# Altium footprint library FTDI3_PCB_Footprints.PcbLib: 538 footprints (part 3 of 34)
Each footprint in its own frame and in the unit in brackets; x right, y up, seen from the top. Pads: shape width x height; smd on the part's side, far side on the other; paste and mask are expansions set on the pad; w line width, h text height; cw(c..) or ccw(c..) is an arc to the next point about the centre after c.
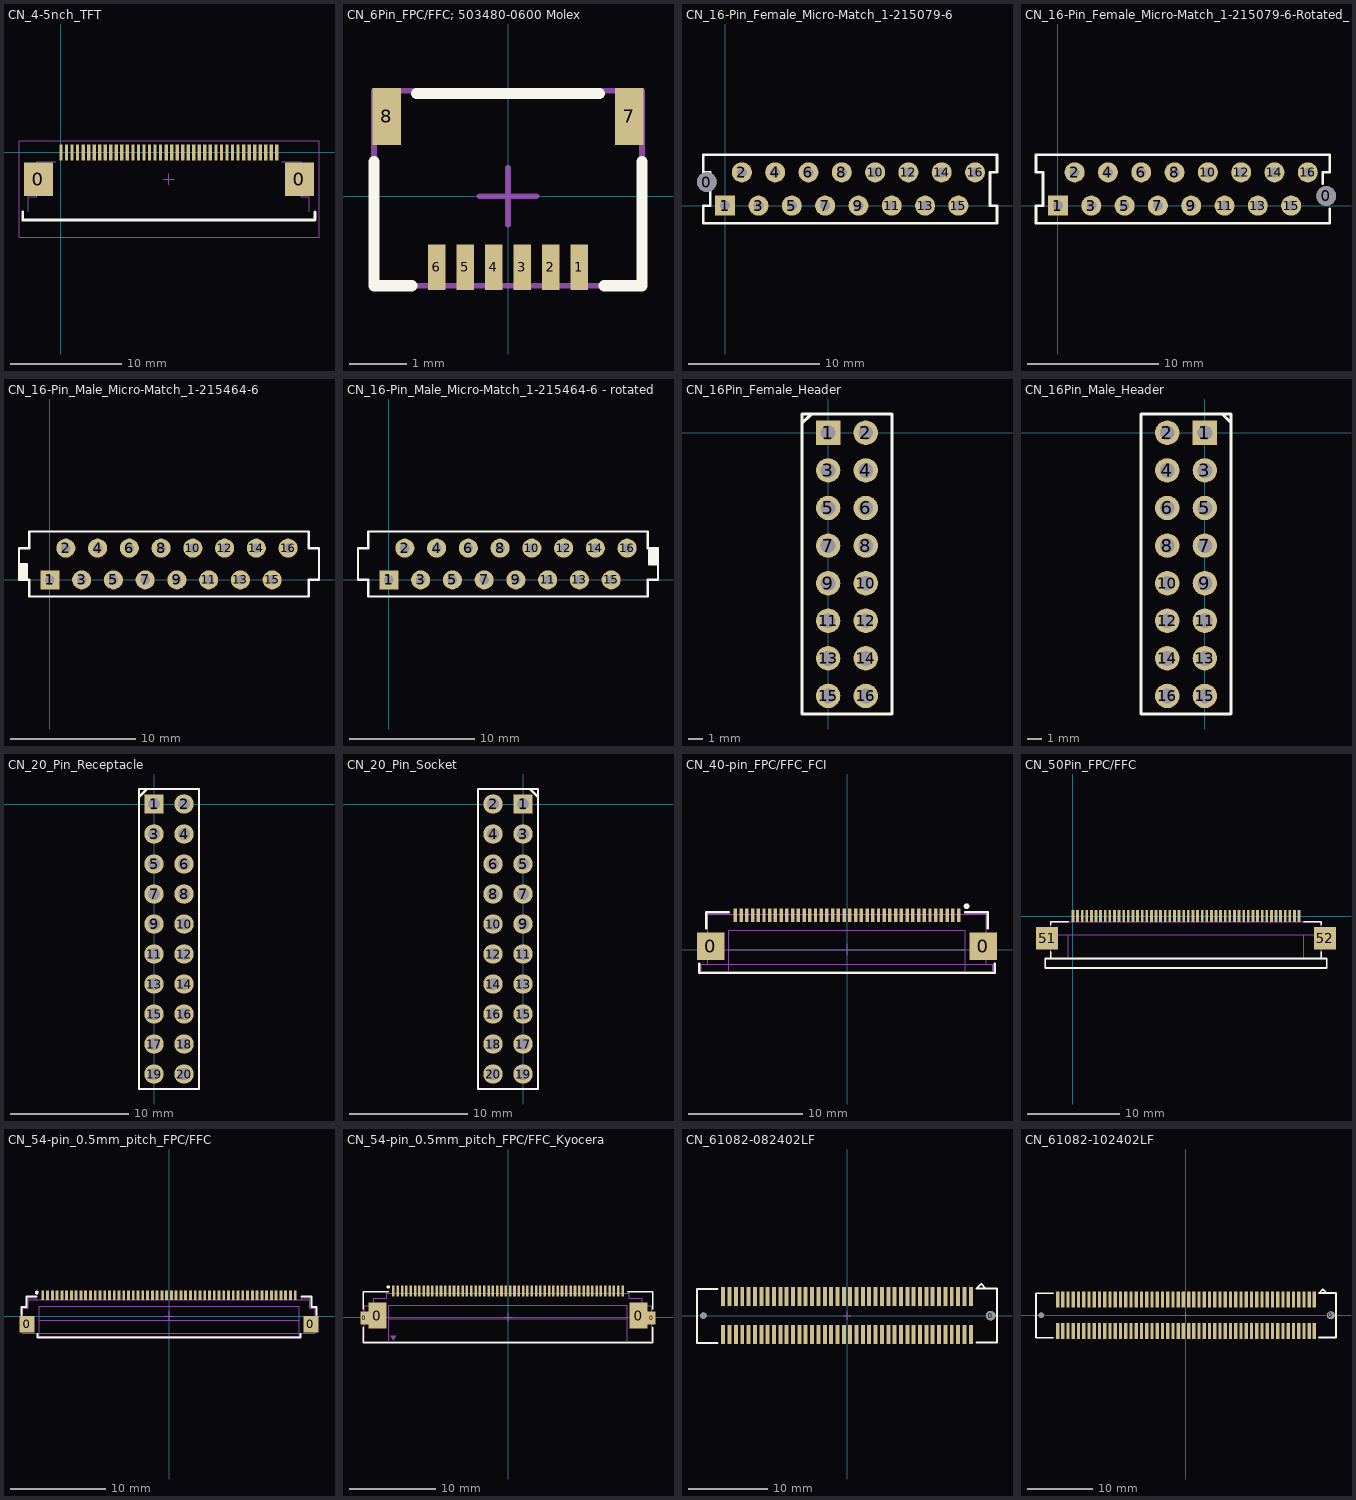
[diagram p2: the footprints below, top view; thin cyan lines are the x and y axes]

## CN_4-5nch_TFT [mm] "Connector for 4.3 and 5\" touch screens"
pads (42):
  rect 2.6x3 smd: 0(-2.04,-2.425) 0(21.54,-2.425)
  rect 0.3x1.45 smd: 1(19.5,0) 2(19,0) 3(18.5,0) 4(18,0) 5(17.5,0) 6(17,0) 7(16.5,0) 8(16,0) 9(15.5,0) 10(15,0) 11(14.5,0) 12(14,0) 13(13.5,0) 14(13,0) 15(12.5,0) 16(12,0) 17(11.5,0) 18(11,0) 19(10.5,0) 20(10,0) 21(9.5,0) 22(9,0) 23(8.5,0) 24(8,0) 25(7.5,0) 26(7,0) 27(6.5,0) 28(6,0) 29(5.5,0) 30(5,0) 31(4.5,0) 32(4,0) 33(3.5,0) 34(3,0) 35(2.5,0) 36(2,0) 37(1.5,0) 38(1,0) 39(0.5,0) 40(0,0)
Top Overlay:
  lines w0.254: -3.45,-5.37 -3.45,-6.1 22.95,-6.1 22.95,-5.37
M13_Assembly_Info:
  lines w0.1: -2.95,-5.35 -2.95,-4 -2.2,-4 -2.2,-0.85 -0.45,-0.85 ; 19.95,-0.85 21.7,-0.85 21.7,-4 22.45,-4 22.45,-5.35
M15_Country_Yard:
  lines w0.1: 9.25,-2.425 10.25,-2.425 ; 9.75,-2.925 9.75,-1.925 ; -3.79,-7.64 23.31,-7.64 23.31,1.04 -3.79,1.04 -3.79,-7.64
3D body: height 2, standoff 0, extent -2.95,-5.35 22.45,-4
3D body: height 2, standoff 0, extent -2.2,-4 21.7,-0.85
3D body: height 0.25, standoff 0, extent 19.375,-0.9 19.625,0.1
3D body: height 0.25, standoff 0, extent 18.875,-0.9 19.125,0.1
3D body: height 0.25, standoff 0, extent 17.375,-0.9 17.625,0.1
3D body: height 0.25, standoff 0, extent 16.875,-0.9 17.125,0.1
3D body: height 0.25, standoff 0, extent 17.875,-0.9 18.125,0.1
3D body: height 0.25, standoff 0, extent 18.375,-0.9 18.625,0.1
3D body: height 0.25, standoff 0, extent 15.375,-0.9 15.625,0.1
3D body: height 0.25, standoff 0, extent 14.875,-0.9 15.125,0.1
3D body: height 0.25, standoff 0, extent 15.875,-0.9 16.125,0.1
3D body: height 0.25, standoff 0, extent 16.375,-0.9 16.625,0.1
3D body: height 0.25, standoff 0, extent 13.375,-0.9 13.625,0.1
3D body: height 0.25, standoff 0, extent 12.875,-0.9 13.125,0.1
3D body: height 0.25, standoff 0, extent 13.875,-0.9 14.125,0.1
3D body: height 0.25, standoff 0, extent 14.375,-0.9 14.625,0.1
3D body: height 0.25, standoff 0, extent 11.375,-0.9 11.625,0.1
3D body: height 0.25, standoff 0, extent 10.875,-0.9 11.125,0.1
3D body: height 0.25, standoff 0, extent 11.875,-0.9 12.125,0.1
3D body: height 0.25, standoff 0, extent 12.375,-0.9 12.625,0.1
3D body: height 0.25, standoff 0, extent 9.375,-0.9 9.625,0.1
3D body: height 0.25, standoff 0, extent 8.875,-0.9 9.125,0.1
3D body: height 0.25, standoff 0, extent 9.875,-0.9 10.125,0.1
3D body: height 0.25, standoff 0, extent 10.375,-0.9 10.625,0.1
3D body: height 0.25, standoff 0, extent 7.375,-0.9 7.625,0.1
3D body: height 0.25, standoff 0, extent 6.875,-0.9 7.125,0.1
3D body: height 0.25, standoff 0, extent 7.875,-0.9 8.125,0.1
3D body: height 0.25, standoff 0, extent 8.375,-0.9 8.625,0.1
3D body: height 0.25, standoff 0, extent 5.375,-0.9 5.625,0.1
3D body: height 0.25, standoff 0, extent 4.875,-0.9 5.125,0.1
3D body: height 0.25, standoff 0, extent 5.875,-0.9 6.125,0.1
3D body: height 0.25, standoff 0, extent 6.375,-0.9 6.625,0.1
3D body: height 0.25, standoff 0, extent 3.375,-0.9 3.625,0.1
3D body: height 0.25, standoff 0, extent 2.875,-0.9 3.125,0.1
3D body: height 0.25, standoff 0, extent 3.875,-0.9 4.125,0.1
3D body: height 0.25, standoff 0, extent 4.375,-0.9 4.625,0.1
3D body: height 0.25, standoff 0, extent 1.375,-0.9 1.625,0.1
3D body: height 0.25, standoff 0, extent 0.875,-0.9 1.125,0.1
3D body: height 0.25, standoff 0, extent 1.875,-0.9 2.125,0.1
3D body: height 0.25, standoff 0, extent 2.375,-0.9 2.625,0.1
3D body: height 0.25, standoff 0, extent -0.125,-0.9 0.125,0.1
3D body: height 0.25, standoff 0, extent 0.375,-0.9 0.625,0.1

## CN_6Pin_FPC/FFC; 503480-0600 Molex [mm] "0.5 mm Pitch, 1.0 mm above the board Top and Bottom Contact, Back-Flip  actuator Flexible Printed Circuit & Flexible Flat Cable ZIF Connectors"
pads (8):
  rect 0.3x0.8 smd: 1(1.25,-1.25) 2(0.75,-1.25) 3(0.25,-1.25) 4(-0.25,-1.25) 5(-0.75,-1.25) 6(-1.25,-1.25)
  rect 0.5x1 smd: 7(2.13,1.4) 8(-2.13,1.4)
Top Overlay:
  lines w0.2: -2.35,0.6 -2.35,-1.57 -1.69,-1.57 ; -1.6,1.8 1.6,1.8 ; 1.69,-1.57 2.35,-1.57 2.35,0.6
M13_Assembly_Info:
  lines w0.1: -2.35,-1.57 -2.35,1.85 2.35,1.85 2.35,-1.57 -2.35,-1.57
M15_Country_Yard:
  lines w0.1: -0.5,0 0.5,0 ; 0,-0.5 0,0.5
3D body: height 1, standoff 0, extent -2.35,-1.57 2.35,1.85

## CN_16-Pin_Female_Micro-Match_1-215079-6 [mil] "Micro-MaTch Board-Board Receptacle; 16-possitions; 0.1\"(2.54mm) pitch; staggered pins; TE Connectivity; 1-215079-6 (8-215079-6)"
height 157.48
pads (17):
  round 59.06 hole 59.06 unplated: 0(-55.12,70.87)
  rect 60x60 hole 30: 1(0,0)
  round 60 hole 30: 2(50,100) 3(100,0) 4(150,100) 5(200,0) 6(250,100) 7(300,0) 8(350,100) 9(400,0) 10(450,100) 11(500,0) 12(550,100) 13(600,0) 14(650,100) 15(700,0) 16(750,100)
Top Overlay:
  lines w7.87: -65.94,-52.36 -65.94,0 -45,0 -45,100 -65.94,100 -65.94,152.36 815.94,152.36 815.94,100 795,100 795,0 815.94,0 815.94,-52.36 -65.94,-52.36
3D body: height 158.08, standoff -117.51, extent -65.35,-46.85 810.63,150

## CN_16-Pin_Female_Micro-Match_1-215079-6-Rotated_180_deg [mil] "Micro-MaTch Board-Board Receptacle; 16-possitions; 0.1\"(2.54mm) pitch; staggered pins; TE Connectivity; 1-215079-6 (8-215079-6)"
height 157.48
pads (17):
  round 59.06 hole 59.06 unplated: 0(805.12,29.13)
  rect 60x60 hole 30: 1(0,0)
  round 60 hole 30: 2(50,100) 3(100,0) 4(150,100) 5(200,0) 6(250,100) 7(300,0) 8(350,100) 9(400,0) 10(450,100) 11(500,0) 12(550,100) 13(600,0) 14(650,100) 15(700,0) 16(750,100)
Top Overlay:
  lines w7.87: 795,66.54 795,100 815.94,100 815.94,152.36 -65.94,152.36 -65.94,100 -45,100 -45,0 -65.94,0 -65.94,-52.36 815.94,-52.36 815.94,-9.45
3D body: height 158.08, standoff -117.51, extent -60.63,-50 815.35,146.85

## CN_16-Pin_Male_Micro-Match_1-215464-6 [mil] "Micro-MaTch Board-Board Header; 16-possitions; 0.1\"(2.54mm) pitch; staggered pins; TE Connectivity; 1-215464-6 (8-215464-6)"
height 271.65
pads (16):
  rect 60x60 hole 30: 1(0,0)
  round 60 hole 30: 2(50,100) 3(100,0) 4(150,100) 5(200,0) 6(250,100) 7(300,0) 8(350,100) 9(400,0) 10(450,100) 11(500,0) 12(550,100) 13(600,0) 14(650,100) 15(700,0) 16(750,100)
Top Overlay:
  rectangle: -97.44,0 -73.03,48.82
  lines w7.87: -97.44,48.82 -73.03,48.82 -73.03,0 -97.44,0 ; -97.44,0 -65,0 -65,-52.36 815,-52.36 815,0 847.44,0 847.44,100 815,100 815,152.36 -65,152.36 -65,100 -97.44,100 -97.44,0
3D body: height 272.25, standoff -123.42, extent -87.01,-47.24 838.19,149.61

## CN_16-Pin_Male_Micro-Match_1-215464-6 - rotated [mil] "Micro-MaTch Board-Board Header; 16-possitions; 0.1\"(2.54mm) pitch; staggered pins; TE Connectivity; 1-215464-6 (8-215464-6)"
height 271.65
pads (16):
  rect 60x60 hole 30: 1(0,0)
  round 60 hole 30: 2(50,100) 3(100,0) 4(150,100) 5(200,0) 6(250,100) 7(300,0) 8(350,100) 9(400,0) 10(450,100) 11(500,0) 12(550,100) 13(600,0) 14(650,100) 15(700,0) 16(750,100)
Top Overlay:
  region: 843.5,98.43 819.09,98.43 819.09,49.61 843.5,49.61
  lines w7.87: 843.5,49.61 819.09,49.61 819.09,98.43 843.5,98.43 ; -97.44,0 -97.44,100 -65,100 -65,152.36 815,152.36 815,100 847.44,100 847.44,0 815,0 815,-52.36 -65,-52.36 -65,0 -97.44,0
3D body: height 272.25, standoff -123.42, extent -86.61,-49.21 838.58,147.64

## CN_16Pin_Female_Header [mil] "Dual Row; Vertical; 0.1\" (2.54mm); Female Header"
height 324.8
pads (16):
  rect 65x65 hole 39.37: 1(0,0)
  round 65 hole 39.37: 2(100,0) 3(0,-100) 4(100,-100) 5(0,-200) 6(100,-200) 7(0,-300) 8(100,-300) 9(0,-400) 10(100,-400) 11(0,-500) 12(100,-500) 13(0,-600) 14(100,-600) 15(0,-700) 16(100,-700)
Top Overlay:
  lines w7.87: -69.88,24.61 -46.26,48.23 ; -69.88,-748.03 170.28,-748.03 170.28,50 -69.88,50 -69.88,-748.03

## CN_16Pin_Male_Header [mil] "Dual Row; Vertical; 0.1\" (2.54mm); Male Header"
height 450.79
pads (16):
  rect 65x65 hole 39.37: 1(0,0)
  round 65 hole 39.37: 2(-100,0) 3(0,-100) 4(-100,-100) 5(0,-200) 6(-100,-200) 7(0,-300) 8(-100,-300) 9(0,-400) 10(-100,-400) 11(0,-500) 12(-100,-500) 13(0,-600) 14(-100,-600) 15(0,-700) 16(-100,-700)
Top Overlay:
  lines w7.87: 46.26,50 69.88,26.38 ; -170.28,-748.03 -170.28,50 69.88,50 69.88,-748.03 -170.28,-748.03

## CN_20_Pin_Receptacle [mil]
pads (20):
  rect 65x65 hole 39.37: 1(0,0)
  round 65 hole 39.37: 2(100,0) 3(0,-100) 4(100,-100) 5(0,-200) 6(100,-200) 7(0,-300) 8(100,-300) 9(0,-400) 10(100,-400) 11(0,-500) 12(100,-500) 13(0,-600) 14(100,-600) 15(0,-700) 16(100,-700) 17(0,-800) 18(100,-800) 19(0,-900) 20(100,-900)
Top Overlay:
  lines w7.87: -48.23,24.61 -24.61,48.23 ; -50,-950 150,-950 150,50 -50,50 -50,-950

## CN_20_Pin_Socket [mil]
pads (20):
  rect 65x65 hole 39.37: 1(0,0)
  round 65 hole 39.37: 2(-100,0) 3(0,-100) 4(-100,-100) 5(0,-200) 6(-100,-200) 7(0,-300) 8(-100,-300) 9(0,-400) 10(-100,-400) 11(0,-500) 12(-100,-500) 13(0,-600) 14(-100,-600) 15(0,-700) 16(-100,-700) 17(0,-800) 18(-100,-800) 19(0,-900) 20(-100,-900)
Top Overlay:
  lines w7.87: 24.61,48.23 48.23,24.61 ; -150,-950 50,-950 50,50 -150,50 -150,-950

## CN_40-pin_FPC/FFC_FCI [mm] "40-pin; 0.5mm pitch; FPC/FFC Connector; FCI Part No. 62684-40210 (Top-Contacts) or 62684-40110 (Bottom Contacts)"
height 2
pads (42):
  rect 2.4x2.4 smd: 0(-11.9,0.3) 0(11.9,0.3)
  rect 0.3x1.2 smd: 1(9.75,3) 2(9.25,3) 3(8.75,3) 4(8.25,3) 5(7.75,3) 6(7.25,3) 7(6.75,3) 8(6.25,3) 9(5.75,3) 10(5.25,3) 11(4.75,3) 12(4.25,3) 13(3.75,3) 14(3.25,3) 15(2.75,3) 16(2.25,3) 17(1.75,3) 18(1.25,3) 19(0.75,3) 20(0.25,3) 21(-0.25,3) 22(-0.75,3) 23(-1.25,3) 24(-1.75,3) 25(-2.25,3) 26(-2.75,3) 27(-3.25,3) 28(-3.75,3) 29(-4.25,3) 30(-4.75,3) 31(-5.25,3) 32(-5.75,3) 33(-6.25,3) 34(-6.75,3) 35(-7.25,3) 36(-7.75,3) 37(-8.25,3) 38(-8.75,3) 39(-9.25,3) 40(-9.75,3)
Top Overlay:
  circle w0.3: c10.442,3.79 r0.098
  lines w0.2: -12.9,-1.25 -12.9,-2.05 12.9,-2.05 12.9,-1.25 ; -12.3,1.86 -12.3,3.25 -10.3,3.25 ; 10.3,3.25 12.3,3.25 12.3,1.86
M13_Assembly_Info:
  lines w0.1: -12.15,-0.2 -12.75,-0.2 -12.75,0.8 -12.15,0.8 ; -10.325,-1.9 -10.325,1.7 10.325,1.7 10.325,-1.9 ; -10.325,0 10.325,0 ; 12.15,-0.2 12.75,-0.2 12.75,0.8 12.15,0.8 ; -12.15,-1.3 -12.75,-1.3 -12.75,-1.9 12.75,-1.9 12.75,-1.3 12.15,-1.3 ; -12.15,-1.3 12.15,-1.3 ; -12.15,-1.3 -12.15,3.1 12.15,3.1 12.15,-1.3
M15_Country_Yard:
  lines w0.1: -0.5,0 0.5,0 ; 0,-0.5 0,0.5
3D body: height 0, standoff 0, extent -12.75,-1.9 12.75,3.1

## CN_50Pin_FPC/FFC [mm]
pads (52):
  rect 0.3x1.3 smd: 1(0,0) 2(0.5,0) 3(1,0) 4(1.5,0) 5(2,0) 6(2.5,0) 7(3,0) 8(3.5,0) 9(4,0) 10(4.5,0) 11(5,0) 12(5.5,0) 13(6,0) 14(6.5,0) 15(7,0) 16(7.5,0) 17(8,0) 18(8.5,0) 19(9,0) 20(9.5,0) 21(10,0) 22(10.5,0) 23(11,0) 24(11.5,0) 25(12,0) 26(12.5,0) 27(13,0) 28(13.5,0) 29(14,0) 30(14.5,0) 31(15,0) 32(15.5,0) 33(16,0) 34(16.5,0) 35(17,0) 36(17.5,0) 37(18,0) 38(18.5,0) 39(19,0) 40(19.5,0) 41(20,0) 42(20.5,0) 43(21,0) 44(21.5,0) 45(22,0) 46(22.5,0) 47(23,0) 48(23.5,0) 49(24,0) 50(24.5,0)
  rect 2.4x2.4 smd: 51(-2.8,-2.4) 52(27.3,-2.4)
Top Overlay:
  lines w0.2: -2.4,-3.9 -2.4,-4.6 ; -2.4,-0.9 -2.4,-0.6 -0.5,-0.6 ; 25,-0.6 26.9,-0.6 26.9,-0.9 ; 26.9,-3.9 26.9,-4.6 ; -2.4,-4.6 -3,-4.6 -3,-5.6 27.5,-5.6 27.5,-4.6 26.9,-4.6 ; -2.4,-4.6 26.9,-4.6
M13_Assembly_Info:
  lines w0.1: -2.4,-2.9 -3,-2.9 -3,-1.9 -2.4,-1.9 ; -2.4,-2 26.9,-2 ; -0.5,-4.6 -0.5,-2 25,-2 25,-4.6 ; 26.9,-2.9 27.5,-2.9 27.5,-1.9 26.9,-1.9 ; -2.4,-4.6 -2.4,-0.6 26.9,-0.6 26.9,-4.6 ; -2.4,-4.6 -3,-4.6 -3,-5.6 27.5,-5.6 27.5,-4.6 26.9,-4.6 ; -2.4,-4.6 26.9,-4.6
3D body: height 0, standoff 0, extent -3,-5.6 27.5,-0.6

## CN_54-pin_0.5mm_pitch_FPC/FFC [mm] "54-pin; 0.5mm pitch; FPC/FFC connector; Molex; 51296-5494"
height 1.3
pads (56):
  rect 1.6x1.7 smd: 0(-14.9,-0.87) 0(14.9,-0.87)
  rect 0.3x1 smd: 1(-13.25,2.18) 2(-12.75,2.18) 3(-12.25,2.18) 4(-11.75,2.18) 5(-11.25,2.18) 6(-10.75,2.18) 7(-10.25,2.18) 8(-9.75,2.18) 9(-9.25,2.18) 10(-8.75,2.18) 11(-8.25,2.18) 12(-7.75,2.18) 13(-7.25,2.18) 14(-6.75,2.18) 15(-6.25,2.18) 16(-5.75,2.18) 17(-5.25,2.18) 18(-4.75,2.18) 19(-4.25,2.18) 20(-3.75,2.18) 21(-3.25,2.18) 22(-2.75,2.18) 23(-2.25,2.18) 24(-1.75,2.18) 25(-1.25,2.18) 26(-0.75,2.18) 27(-0.25,2.18) 28(0.25,2.18) 29(0.75,2.18) 30(1.25,2.18) 31(1.75,2.18) 32(2.25,2.18) 33(2.75,2.18) 34(3.25,2.18) 35(3.75,2.18) 36(4.25,2.18) 37(4.75,2.18) 38(5.25,2.18) 39(5.75,2.18) 40(6.25,2.18) 41(6.75,2.18) 42(7.25,2.18) 43(7.75,2.18) 44(8.25,2.18) 45(8.75,2.18) 46(9.25,2.18) 47(9.75,2.18) 48(10.25,2.18) 49(10.75,2.18) 50(11.25,2.18) 51(11.75,2.18) 52(12.25,2.18) 53(12.75,2.18) 54(13.25,2.18)
Top Overlay:
  circle w0.2: c-13.88,2.47 r0.1
  lines w0.2: -15.5,0.09 -15.5,0.95 -14.95,0.95 -14.95,2.05 -13.89,2.05 ; -13.8,-1.9 -13.8,-2.25 13.8,-2.25 13.8,-1.9 ; 13.89,2.05 14.95,2.05 14.95,0.95 15.5,0.95 15.5,0.09
M13_Assembly_Info:
  lines w0.1: -14.8,-1.8 14.8,-1.8 ; -13.65,-1.8 -13.65,-2.1 ; 13.65,-1.8 13.65,-2.1 ; -14.8,1.7 -14.8,1.9 -13.94,1.9 -13.94,1.7 ; -14.8,1.7 -14.8,0.8 -15.35,0.8 -15.35,-1.8 15.35,-1.8 15.35,0.8 14.8,0.8 14.8,1.7 ; -14.8,1.7 -13.94,1.7 ; -13.94,1.7 14.8,1.7 ; -13.65,-2.1 13.65,-2.1 ; -13.65,-2.1 -13.65,-0.45 ; -13.65,-0.45 13.65,-0.45 ; -13.65,-0.45 -13.65,1.05 0,1.05 13.65,1.05 13.65,-0.45 ; 13.65,-2.1 13.65,-0.45 ; 14.8,1.7 13.94,1.7 13.94,1.9 14.8,1.9 14.8,1.7
M15_Country_Yard:
  lines w0.1: -0.5,0 0.5,0 ; 0,-0.5 0,0.5
3D body: height 1.27, standoff -0.03, extent -15.34,-2.08 15.36,2.22

## CN_54-pin_0.5mm_pitch_FPC/FFC_Kyocera [mm] "54-pin; 0.5mm pitch; FPC/FFC connector; Kyocera; 046240054005800+"
height 2
pads (58):
  rect 0.9x1.5 smd: 0(-16.6,-0.1) 0(16.6,-0.1)
  rect 2.1x3 smd: 0(-15.1,0.2) 0(15.1,0.2)
  rect 0.3x1.3 smd: 1(-13.25,3.05) 2(-12.75,3.05) 3(-12.25,3.05) 4(-11.75,3.05) 5(-11.25,3.05) 6(-10.75,3.05) 7(-10.25,3.05) 8(-9.75,3.05) 9(-9.25,3.05) 10(-8.75,3.05) 11(-8.25,3.05) 12(-7.75,3.05) 13(-7.25,3.05) 14(-6.75,3.05) 15(-6.25,3.05) 16(-5.75,3.05) 17(-5.25,3.05) 18(-4.75,3.05) 19(-4.25,3.05) 20(-3.75,3.05) 21(-3.25,3.05) 22(-2.75,3.05) 23(-2.25,3.05) 24(-1.75,3.05) 25(-1.25,3.05) 26(-0.75,3.05) 27(-0.25,3.05) 28(0.25,3.05) 29(0.75,3.05) 30(1.25,3.05) 31(1.75,3.05) 32(2.25,3.05) 33(2.75,3.05) 34(3.25,3.05) 35(3.75,3.05) 36(4.25,3.05) 37(4.75,3.05) 38(5.25,3.05) 39(5.75,3.05) 40(6.25,3.05) 41(6.75,3.05) 42(7.25,3.05) 43(7.75,3.05) 44(8.25,3.05) 45(8.75,3.05) 46(9.25,3.05) 47(9.75,3.05) 48(10.25,3.05) 49(10.75,3.05) 50(11.25,3.05) 51(11.75,3.05) 52(12.25,3.05) 53(12.75,3.05) 54(13.25,3.05)
Top Overlay:
  circle w0.2: c-13.85,3.5 r0.1
  lines w0.2: -16.75,-1.15 -16.75,-2.95 16.75,-2.95 16.75,-1.15 ; -16.75,0.94 -16.75,2.95 -13.85,2.95 ; 13.85,2.95 16.75,2.95 16.75,0.94
M13_Assembly_Info:
  region: -13.6,-2.15 -12.9,-2.15 -13.25,-2.65
  lines w0.1: -13.8,-2.8 -13.8,1.4 13.8,1.4 13.8,-2.8 ; -13.8,-0.2 13.8,-0.2 ; -16.6,-2.8 16.6,-2.8 16.6,1.35 15.5,1.35 15.5,2.2 14,2.2 14,2.8 -14,2.8 -14,2.2 -15.5,2.2 -15.5,1.35 -16.6,1.35 -16.6,-2.8
M15_Country_Yard:
  lines w0.1: -0.5,0 0.5,0 ; 0,-0.5 0,0.5

## CN_61082-082402LF [mm] "FCI, 2x40 pins, 0.8mm pitch, 7.7mm height, Board to Board Receptacle"
height 7.7
pads (82):
  round 0.8 hole 0.8 unplated: 0(-18.1,0)
  round 1.2 hole 1.2 unplated: 0(18.1,0)
  rect 0.5x2.4 smd: 1(15.6,2.4) 2(15.6,-2.4) 3(14.8,2.4) 4(14.8,-2.4) 5(14,2.4) 6(14,-2.4) 7(13.2,2.4) 8(13.2,-2.4) 9(12.4,2.4) 10(12.4,-2.4) 11(11.6,2.4) 12(11.6,-2.4) 13(10.8,2.4) 14(10.8,-2.4) 15(10,2.4) 16(10,-2.4) 17(9.2,2.4) 18(9.2,-2.4) 19(8.4,2.4) 20(8.4,-2.4) 21(7.6,2.4) 22(7.6,-2.4) 23(6.8,2.4) 24(6.8,-2.4) 25(6,2.4) 26(6,-2.4) 27(5.2,2.4) 28(5.2,-2.4) 29(4.4,2.4) 30(4.4,-2.4) 31(3.6,2.4) 32(3.6,-2.4) 33(2.8,2.4) 34(2.8,-2.4) 35(2,2.4) 36(2,-2.4) 37(1.2,2.4) 38(1.2,-2.4) 39(0.4,2.4) 40(0.4,-2.4) 41(-0.4,2.4) 42(-0.4,-2.4) 43(-1.2,2.4) 44(-1.2,-2.4) 45(-2,2.4) 46(-2,-2.4) 47(-2.8,2.4) 48(-2.8,-2.4) 49(-3.6,2.4) 50(-3.6,-2.4) 51(-4.4,2.4) 52(-4.4,-2.4) 53(-5.2,2.4) 54(-5.2,-2.4) 55(-6,2.4) 56(-6,-2.4) 57(-6.8,2.4) 58(-6.8,-2.4) 59(-7.6,2.4) 60(-7.6,-2.4) 61(-8.4,2.4) 62(-8.4,-2.4) 63(-9.2,2.4) 64(-9.2,-2.4) 65(-10,2.4) 66(-10,-2.4) 67(-10.8,2.4) 68(-10.8,-2.4) 69(-11.6,2.4) 70(-11.6,-2.4) 71(-12.4,2.4) 72(-12.4,-2.4) 73(-13.2,2.4) 74(-13.2,-2.4) 75(-14,2.4) 76(-14,-2.4) 77(-14.8,2.4) 78(-14.8,-2.4) 79(-15.6,2.4) 80(-15.6,-2.4)
Top Overlay:
  lines w0.254: -16.3,-3.425 -18.9,-3.425 -18.9,3.375 -16.3,3.375 ; 16.3,-3.4 18.9,-3.4 18.9,3.4 16.3,3.4 16.9,4 17.5,3.4
M15_Country_Yard:
  lines w0.1: -0.5,0 0.5,0 ; 0,-0.5 0,0.5

## CN_61082-102402LF [mm] "FCI, 2x50 pins, 0.8mm pitch, 7.7mm height, Board to Board Receptacle"
height 7.7
pads (102):
  round 0.8 hole 0.8 unplated: 0(-22.1,0)
  round 1.2 hole 1.2 unplated: 0(22.1,0)
  rect 0.5x2.4 smd: 1(19.6,2.4) 2(19.6,-2.4) 3(18.8,2.4) 4(18.8,-2.4) 5(18,2.4) 6(18,-2.4) 7(17.2,2.4) 8(17.2,-2.4) 9(16.4,2.4) 10(16.4,-2.4) 11(15.6,2.4) 12(15.6,-2.4) 13(14.8,2.4) 14(14.8,-2.4) 15(14,2.4) 16(14,-2.4) 17(13.2,2.4) 18(13.2,-2.4) 19(12.4,2.4) 20(12.4,-2.4) 21(11.6,2.4) 22(11.6,-2.4) 23(10.8,2.4) 24(10.8,-2.4) 25(10,2.4) 26(10,-2.4) 27(9.2,2.4) 28(9.2,-2.4) 29(8.4,2.4) 30(8.4,-2.4) 31(7.6,2.4) 32(7.6,-2.4) 33(6.8,2.4) 34(6.8,-2.4) 35(6,2.4) 36(6,-2.4) 37(5.2,2.4) 38(5.2,-2.4) 39(4.4,2.4) 40(4.4,-2.4) 41(3.6,2.4) 42(3.6,-2.4) 43(2.8,2.4) 44(2.8,-2.4) 45(2,2.4) 46(2,-2.4) 47(1.2,2.4) 48(1.2,-2.4) 49(0.4,2.4) 50(0.4,-2.4) 51(-0.4,2.4) 52(-0.4,-2.4) 53(-1.2,2.4) 54(-1.2,-2.4) 55(-2,2.4) 56(-2,-2.4) 57(-2.8,2.4) 58(-2.8,-2.4) 59(-3.6,2.4) 60(-3.6,-2.4) 61(-4.4,2.4) 62(-4.4,-2.4) 63(-5.2,2.4) 64(-5.2,-2.4) 65(-6,2.4) 66(-6,-2.4) 67(-6.8,2.4) 68(-6.8,-2.4) 69(-7.6,2.4) 70(-7.6,-2.4) 71(-8.4,2.4) 72(-8.4,-2.4) 73(-9.2,2.4) 74(-9.2,-2.4) 75(-10,2.4) 76(-10,-2.4) 77(-10.8,2.4) 78(-10.8,-2.4) 79(-11.6,2.4) 80(-11.6,-2.4) 81(-12.4,2.4) 82(-12.4,-2.4) 83(-13.2,2.4) 84(-13.2,-2.4) 85(-14,2.4) 86(-14,-2.4) 87(-14.8,2.4) 88(-14.8,-2.4) 89(-15.6,2.4) 90(-15.6,-2.4) 91(-16.4,2.4) 92(-16.4,-2.4) 93(-17.2,2.4) 94(-17.2,-2.4) 95(-18,2.4) 96(-18,-2.4) 97(-18.8,2.4) 98(-18.8,-2.4) 99(-19.6,2.4) 100(-19.6,-2.4)
Top Overlay:
  lines w0.254: -20.3,-3.425 -22.9,-3.425 -22.9,3.375 -20.3,3.375 ; 20.3,-3.4 22.9,-3.4 22.9,3.4 20.3,3.4 20.9,4 21.5,3.4
M15_Country_Yard:
  lines w0.1: -0.5,0 0.5,0 ; 0,-0.5 0,0.5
